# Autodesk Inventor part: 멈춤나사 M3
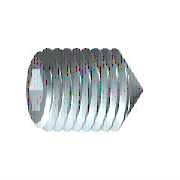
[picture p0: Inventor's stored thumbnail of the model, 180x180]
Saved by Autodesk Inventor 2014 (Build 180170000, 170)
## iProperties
IsCustomPart: 1
Created: 2012-02
Part Number: 멈춤나사 M3
Material: 강철, 연강
Description: 6각 소켓 머리 없는 멈춤 나사
Document SubType Name: Modeling
Standard: KS B 1028
Designer: mduedu
Standards Organization: KS
Language: ko-KR
Size Designation: 원추점 M3x6
Categories: <MemberInstance><Categories><Category DisplayName="조임쇠" InternalName="e4da775c-781d-43d5-af7c-5136215cf5a6" Mnemonic="FSTN"><Category DisplayName="볼트" InternalN
Density: 1 g/cm^3
Appearance: Yellow
Author: mduedu
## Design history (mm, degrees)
sketch "스케치1"
  geometry: L1 (0, 0)-(3.5, 0); L2 (6, 0.866)-(6, 1.5); L3 (6, 1.5)-(0, 1.5); L4 (6, 0.866)-(4, 0.866); L5 (4, 0.866)-(3.5, 0); L6 (0, -0.3)-(0, 1.8) reference; L7 (0, 1.5)-(0, 0)
  constraints: 13 end point, 3 parallel, 1 collinear, 1 perpendicular, 1 point on line
  dimensions: "d0" = 2 distance of L2.start L4.end (= INTI); "d1" = 60 deg angle of L5 L1; "d2" = 3 diameter of L3 L1 (= NND); "d3" = 1.73205 diameter of L4 L1 (= 1.1547 x SW); "d5" = 6 distance from line of L2 L3.end (= NLG)
revolve "본체" sketch "스케치1" stored, may be unused: angle "d6" = 90 deg
sketch "스케치2"
  geometry: L1 (-0.433, 0.75)-(0.433, 0.75); L2 (0.433, 0.75)-(0.866, 0); L3 (0.866, 0)-(0.433, -0.75); L4 (0.433, -0.75)-(-0.433, -0.75); L5 (-0.433, -0.75)-(-0.866, 0); L6 (-0.866, 0)-(-0.433, 0.75); 3 further points
  constraints: 12 end point, 1 coincident, 1 horizontal, 13 other
extrude "슬롯" join sketch "스케치2" taper "d7" = 0 deg; stored distance "d21" = 10
workaxis "Work Axis1"
workplane "Work Plane1"
workpoint "Work Point1"
  workaxis "Work Axis2"
body "Solid1"
feature "스레드" dims "d12" = 6 (= NLG), "d13" = 0
chamfer "모따기1" distance "d8" = 1.35 (computed from NND, SPD, FAWI); stored, may be unused: angle "d9" = 45 deg (= FAWI), second distance "d34" = 1.35 (computed from NND, SPD, FAWI)
chamfer "모따기2" distance "d10" = 0.30673 (= -0.5 x GD1 + 0.5 x NND); stored, may be unused: angle "d11" = 45 deg (= FAWI), second distance "d35" = 0.30673 (= -0.5 x GD1 + 0.5 x NND)
other parameters: "NND" = 3 [user parameter; used in 5 equation terms], "NLG" = 6 [user parameter; used in 2 equation terms], "INTI" = 2 [user parameter; used in 1 equation term], "FAWI" = 45 deg [user parameter; used in 4 equation terms], "SW" = 1.5 [user parameter; used in 2 equation terms], "GD1" = 2.38655 (= THREADDIA - 1.2269 x PTC) [user parameter; used in 2 equation terms], "d4" = 0, "FAWI1" = 45 deg [user parameter], "SPD" = 0.3 [user parameter; used in 2 equation terms], "d36" = 0, "d37" = 0, "GUL" = 0.30673 (= 0.61345 x PTC) [user parameter], "TOA" = 30 deg [user parameter], "THREADDIA" = 3 [user parameter; used in 1 equation term], "PTC" = 0.5 [user parameter; used in 4 equation terms], "GAL" = 0.30673 (= 0.61345 x PTC) [user parameter], "E0" = 1.7325 (= 1.155 x SW) [user parameter]
